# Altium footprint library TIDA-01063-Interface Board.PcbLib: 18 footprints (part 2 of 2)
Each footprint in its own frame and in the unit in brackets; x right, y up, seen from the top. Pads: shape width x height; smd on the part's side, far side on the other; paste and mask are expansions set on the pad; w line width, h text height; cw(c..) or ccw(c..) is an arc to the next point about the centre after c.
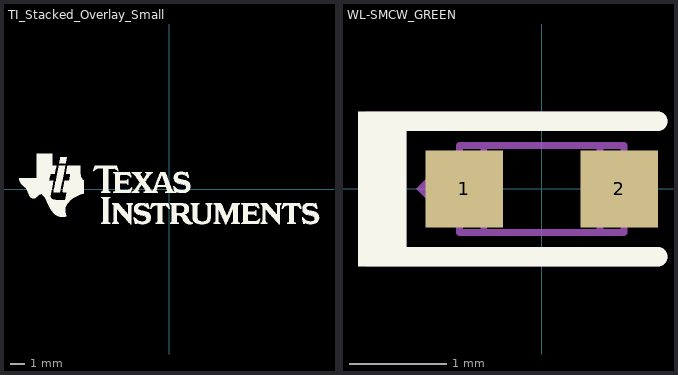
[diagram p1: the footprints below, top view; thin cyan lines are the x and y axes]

## TI_Stacked_Overlay_Small [mil]
Top Overlay:
  drawing of 18 lines, arcs and shapes, not listed

## WL-SMCW_GREEN [mm] "WURTH"
height 0.8
pads (2):
  rect 0.8x0.8 smd: 1(-0.8,0) 2(0.8,0)
Top Overlay:
  rectangle: -1.9,-0.8 -1.4,0.8
  lines w0.2: -1.6,-0.7 1.2,-0.7 ; -1.6,0.7 1.2,0.7
Mechanical 5:
  region: -0.9,-0.4 -0.9,0.4 -1.3,0
  lines w0.2: -1.65,-0.7 -1.65,0.55 ; 1.2,-0.7 -1.5,-0.7 ; 1.2,0.7 -1.5,0.7 ; -1.5,-0.7 -1.8,-0.7 -1.8,0.7 -1.5,0.7 ; -1.5,-0.7 -1.5,0.7
  text ".Designator" at -0.8,-0.3 h0.45
Mechanical 13:
  lines w0.07: -0.6,-0.45 -0.6,0.45 ; 0.6,-0.45 0.6,0.45 ; -0.85,-0.45 0.85,-0.45 0.85,0.45 -0.85,0.45 -0.85,-0.45
3D body: height 0.36, standoff 0.35, extent -0.599,-0.449 0.599,0.449
3D body: height 0.8, standoff 0.35, extent -0.599,-0.449 0.599,0.449
3D body: height 0.35, standoff 0, extent 0.601,-0.449 0.849,0.449
3D body: height 0.35, standoff 0, extent -0.599,-0.449 0.599,0.449
3D body: height 0.35, standoff 0, extent -0.849,-0.449 -0.601,0.449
